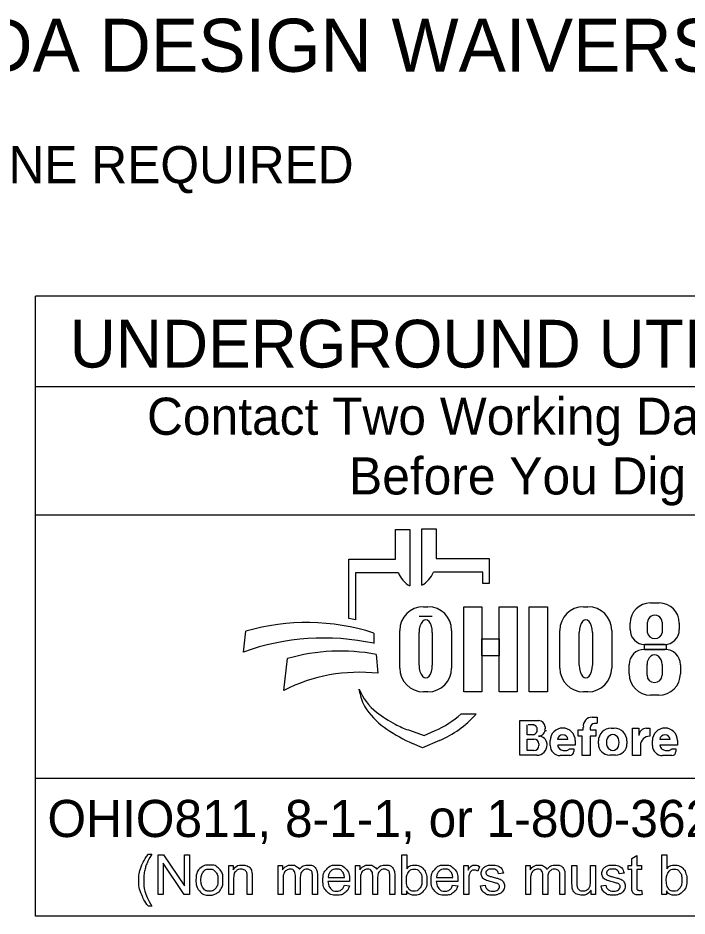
# Model space of a CAD drawing. Extents: x 0 to 34, y 0 to 22.
# Drawn here: x 2.311 to 4.831, y 2.143 to 5.529 of the extents above; entities that cross this region are included whole.
import ezdxf

# ---------------------------------------------------------------- set-up
doc = ezdxf.new("R2010")
doc.units = 0
doc.layers.add('SH_Data', color=7, linetype='Continuous')
doc.layers.add('SH_Text', color=7, linetype='Continuous')

msp = doc.modelspace()

# ---------------------------------------------------------------- linework, layer by layer
at = {"layer": 'SH_Data'}
for p, q in [((2.3775, 2.1428), (2.3775, 4.4803)), ((6.6275, 4.4803), (2.3775, 4.4803)), ((2.3775, 4.1387), (6.6275, 4.1387)), ((2.3775, 3.6553), (6.6275, 3.6553)), ((6.6275, 2.6607), (2.3775, 2.6607)), ((6.6275, 2.1428), (2.3775, 2.1428))]:
    msp.add_line(p, q, dxfattribs=at)
at = {"layer": 'SH_Text'}
for p, q in [((3.7335, 3.4883), (3.7335, 3.5998)), ((3.7335, 3.5998), (3.7872, 3.5998)), ((3.7872, 3.5998), (3.7872, 3.3877)), ((3.8329, 3.39), (3.8329, 3.6021)), ((3.8329, 3.6021), (3.8865, 3.6021)), ((3.8865, 3.6021), (3.8865, 3.4906)), ((3.5576, 3.2644), (3.5576, 3.4883)), ((3.5576, 3.4883), (3.7335, 3.4883)), ((3.8865, 3.4906), (4.0857, 3.4906)), ((4.0857, 3.4906), (4.0857, 3.3968)), ((3.5828, 3.4369), (3.5828, 3.26)), ((3.7439, 3.4369), (3.5828, 3.4369)), ((4.0625, 3.4392), (3.8761, 3.4392)), ((4.0625, 3.3968), (4.0625, 3.4392)), ((4.0857, 3.3968), (4.0625, 3.3968)), ((4.6931, 3.3231), (4.7258, 3.3231)), ((3.8385, 3.3091), (3.8551, 3.3091)), ((4.4416, 3.3091), (4.4581, 3.3091)), ((3.8718, 3.2721), (3.822, 3.2721)), ((4.683, 3.2111), (4.683, 3.2504)), ((4.7371, 3.2504), (4.7371, 3.2111)), ((3.7491, 3.0776), (3.7491, 3.2196)), ((3.9445, 3.2196), (3.9445, 3.0776)), ((4.3521, 3.0776), (4.3521, 3.2196)), ((4.5476, 3.2196), (4.5476, 3.0776)), ((4.6168, 3.2225), (4.6168, 3.2468)), ((4.8022, 3.2468), (4.8022, 3.2225)), ((3.1602, 3.1381), (3.1696, 3.2162)), ((3.6509, 3.2097), (3.6509, 3.1709)), ((3.822, 3.089), (3.822, 3.2114)), ((3.8718, 3.2114), (3.8718, 3.089)), ((4.425, 3.089), (4.425, 3.2114)), ((4.4748, 3.2114), (4.4748, 3.089)), ((4.7462, 3.1665), (4.6728, 3.1665)), ((3.6608, 3.1291), (3.6671, 3.0582)), ((4.671, 3.1482), (4.7483, 3.1482)), ((3.312, 2.9936), (3.3267, 3.1137)), ((4.6131, 3.0563), (4.6131, 3.0903)), ((4.6806, 3.0503), (4.6806, 3.0912)), ((4.7374, 3.0912), (4.7374, 3.0503)), ((4.8062, 3.0903), (4.8062, 3.0563)), ((3.5997, 2.9807), (3.5967, 2.9986)), ((3.8551, 2.9882), (3.8385, 2.9882)), ((4.4581, 2.9882), (4.4416, 2.9882)), ((4.7252, 2.9753), (4.6941, 2.9753)), ((3.98, 2.9048), (4.0375, 2.9048)), ((4.2013, 2.749), (4.2013, 2.8798)), ((4.2013, 2.8798), (4.2725, 2.8798)), ((4.4739, 2.8926), (4.4934, 2.8926)), ((4.4934, 2.8926), (4.4934, 2.8696)), ((3.7816, 2.8444), (3.841, 2.8239)), ((4.2293, 2.8263), (4.2293, 2.8632)), ((4.2545, 2.8632), (4.2332, 2.8632)), ((4.2963, 2.856), (4.2963, 2.8481)), ((4.4213, 2.8212), (4.4213, 2.8442)), ((4.4213, 2.8442), (4.4406, 2.8442)), ((4.4406, 2.8442), (4.4406, 2.8546)), ((4.4667, 2.8526), (4.4667, 2.8442)), ((4.4667, 2.8442), (4.4883, 2.8442)), ((4.4934, 2.8691), (4.4832, 2.8691)), ((4.4883, 2.8442), (4.4883, 2.8212)), ((4.5451, 2.8508), (4.5573, 2.8508)), ((4.6254, 2.7478), (4.6254, 2.8505)), ((4.6254, 2.8505), (4.6499, 2.8505)), ((4.6499, 2.8505), (4.6499, 2.8237)), ((4.6772, 2.8505), (4.691, 2.8505)), ((4.691, 2.8505), (4.691, 2.8209)), ((3.841, 2.8239), (3.8821, 2.8417)), ((4.2487, 2.8263), (4.2293, 2.8263)), ((4.4362, 2.8212), (4.4213, 2.8212)), ((4.4362, 2.7478), (4.4362, 2.8212)), ((4.4883, 2.8212), (4.4667, 2.8212)), ((4.4667, 2.8212), (4.4667, 2.7478)), ((3.835, 2.7769), (3.7976, 2.7934)), ((3.8983, 2.8044), (3.835, 2.7769)), ((4.2293, 2.7669), (4.2293, 2.8097)), ((4.2293, 2.8097), (4.2548, 2.8097)), ((4.2729, 2.7916), (4.2729, 2.7853)), ((4.3043, 2.7887), (4.3043, 2.7884)), ((4.3159, 2.7858), (4.3159, 2.8042)), ((4.3824, 2.8082), (4.3439, 2.8082)), ((4.4104, 2.7866), (4.344, 2.7866)), ((4.4104, 2.8042), (4.4104, 2.7866)), ((4.4973, 2.7922), (4.4973, 2.8029)), ((4.6051, 2.8029), (4.6051, 2.7922)), ((4.6559, 2.786), (4.6559, 2.7478)), ((4.7008, 2.7858), (4.7008, 2.8042)), ((4.7674, 2.8082), (4.7288, 2.8082)), ((4.7953, 2.7866), (4.7289, 2.7866)), ((4.7953, 2.8042), (4.7953, 2.7866)), ((4.265, 2.749), (4.2013, 2.749)), ((4.2546, 2.7669), (4.2293, 2.7669)), ((4.3892, 2.7478), (4.3538, 2.7478)), ((4.3649, 2.7673), (4.379, 2.7673)), ((4.3876, 2.7729), (4.4045, 2.7729)), ((4.4045, 2.7729), (4.4045, 2.7631)), ((4.4667, 2.7478), (4.4362, 2.7478)), ((4.5623, 2.7494), (4.5401, 2.7494)), ((4.6559, 2.7478), (4.6254, 2.7478)), ((4.7742, 2.7478), (4.7388, 2.7478)), ((4.7498, 2.7673), (4.7639, 2.7673)), ((4.7725, 2.7729), (4.7894, 2.7729)), ((4.7894, 2.7729), (4.7894, 2.7631))]:
    msp.add_line(p, q, dxfattribs=at)
for points in [[(3.991, 3.3081), (4.0589, 3.3081), (4.0589, 2.9881), (3.991, 2.9881)], [(4.1231, 3.3081), (4.1911, 3.3081), (4.1911, 2.9881), (4.1231, 2.9881)], [(4.2364, 3.3081), (4.3052, 3.3081), (4.3052, 2.9881), (4.2364, 2.9881)], [(4.0589, 3.1882), (4.1231, 3.1882), (4.1231, 3.1242), (4.0589, 3.1242)], [(4.6706, 3.1665), (4.7523, 3.1665), (4.7523, 3.1481), (4.6706, 3.1481)]]:
    msp.add_lwpolyline(points, close=True, dxfattribs=at)
for points in [[(2.8021, 2.3766), (2.8153, 2.3766)], [(2.8389, 2.2239), (2.8389, 2.3741), (2.8592, 2.3741), (2.9382, 2.2561), (2.9382, 2.3741), (2.9572, 2.3741), (2.9572, 2.2239), (2.9369, 2.2239), (2.8579, 2.3419), (2.8579, 2.2239), (2.8389, 2.2239)], [(3.7743, 2.2239), (3.7573, 2.2239), (3.7573, 2.3741), (3.7757, 2.3741), (3.7757, 2.3206)], [(4.6233, 2.2558), (4.6233, 2.3185), (4.6097, 2.3185), (4.6097, 2.3328), (4.6233, 2.3328), (4.6233, 2.3597), (4.6417, 2.3708), (4.6417, 2.3328), (4.6601, 2.3328), (4.6601, 2.3185), (4.6417, 2.3185), (4.6417, 2.2547)], [(4.7534, 2.2239), (4.7363, 2.2239), (4.7363, 2.3741), (4.7548, 2.3741), (4.7548, 2.3206)], [(3.1048, 2.2239), (3.1048, 2.3328), (3.1214, 2.3328), (3.1214, 2.3173)], [(3.2912, 2.2239), (3.2912, 2.3328), (3.3077, 2.3328), (3.3077, 2.3174)], [(3.5826, 2.2239), (3.5826, 2.3328), (3.5991, 2.3328), (3.5991, 2.3174)], [(3.9904, 2.2239), (3.9904, 2.3328), (4.007, 2.3328), (4.007, 2.3163)], [(4.0495, 2.3293), (4.043, 2.3122)], [(4.1394, 2.3046), (4.1213, 2.3022)], [(4.2236, 2.2239), (4.2236, 2.3328), (4.2401, 2.3328), (4.2401, 2.3174)], [(4.3979, 2.2654), (4.3979, 2.3328), (4.4164, 2.3328), (4.4164, 2.2724)], [(4.4676, 2.2745), (4.4676, 2.3328), (4.4861, 2.3328), (4.4861, 2.2239), (4.4696, 2.2239)], [(4.594, 2.3046), (4.5759, 2.3022)], [(3.1233, 2.2833), (3.1233, 2.2239), (3.1048, 2.2239)], [(3.1932, 2.2908), (3.1932, 2.2239), (3.1748, 2.2239), (3.1748, 2.2901)], [(3.3097, 2.2803), (3.3097, 2.2239), (3.2912, 2.2239)], [(3.3743, 2.2871), (3.3743, 2.2239), (3.3559, 2.2239), (3.3559, 2.2946)], [(3.4388, 2.2986), (3.4388, 2.2239), (3.4203, 2.2239), (3.4203, 2.2924)], [(3.56, 2.2736), (3.4788, 2.2736)], [(3.4799, 2.2887), (3.5406, 2.2887)], [(3.601, 2.2803), (3.601, 2.2239), (3.5826, 2.2239)], [(3.6657, 2.2871), (3.6657, 2.2239), (3.6473, 2.2239), (3.6473, 2.2946)], [(3.7301, 2.2986), (3.7301, 2.2239), (3.7117, 2.2239), (3.7117, 2.2924)], [(3.968, 2.2736), (3.8868, 2.2736)], [(3.8879, 2.2887), (3.9486, 2.2887)], [(4.0088, 2.2809), (4.0088, 2.2239), (3.9904, 2.2239)], [(4.242, 2.2803), (4.242, 2.2239), (4.2236, 2.2239)], [(4.3067, 2.2871), (4.3067, 2.2239), (4.2883, 2.2239), (4.2883, 2.2946)], [(4.3711, 2.2986), (4.3711, 2.2239), (4.3527, 2.2239), (4.3527, 2.2924)], [(3.5404, 2.2591), (3.5595, 2.2567)], [(3.7743, 2.2375), (3.7743, 2.2239)], [(3.9484, 2.2591), (3.9675, 2.2567)], [(4.053, 2.2564), (4.0712, 2.2593)], [(4.4696, 2.2239), (4.4696, 2.24)], [(4.5076, 2.2564), (4.5258, 2.2593)], [(4.6601, 2.2404), (4.6628, 2.2241)], [(4.7534, 2.2375), (4.7534, 2.2239)], [(2.8153, 2.1798), (2.8021, 2.1798)]]:
    msp.add_lwpolyline(points, dxfattribs=at)
for centre, radius, start, end in [((3.8353, 3.4736), 0.0985, 201.9296, 240.7469), ((3.7847, 3.476), 0.0985, 299.2531, 338.0704), ((4.6931, 3.2468), 0.0763, 90, 180), ((4.7258, 3.2468), 0.0763, 0, 90), ((3.8385, 3.2196), 0.0895, 90, 180), ((3.8551, 3.2196), 0.0895, 0, 90), ((4.4416, 3.2196), 0.0895, 90, 180), ((4.4581, 3.2196), 0.0895, 0, 90), ((3.4295, 2.4554), 0.8191, 79.2074, 81.0007), ((3.3997, 2.4302), 0.8191, 72.1402, 106.3144), ((4.6728, 3.2225), 0.056, 180, 270), ((4.7462, 3.2225), 0.056, 270, 0), ((3.4628, 2.2991), 0.8919, 77.8238, 109.8274), ((3.5267, 2.4094), 0.7322, 79.44, 105.8467), ((4.671, 3.0903), 0.0579, 90, 180), ((4.7483, 3.0903), 0.0579, 0, 90), ((3.5987, 2.4262), 0.6357, 83.8248, 116.8021), ((3.8385, 3.0776), 0.0895, 180, 270), ((3.8551, 3.0776), 0.0895, 270, 0), ((4.4416, 3.0776), 0.0895, 180, 270), ((4.4581, 3.0776), 0.0895, 270, 0), ((4.6941, 3.0563), 0.081, 180, 270), ((4.7252, 3.0563), 0.081, 270, 0), ((3.7841, 3.0707), 0.2008, 201.0457, 232.5314), ((3.741, 3.0048), 0.1433, 189.6817, 216.0884), ((3.8747, 3.1022), 0.3088, 216.0884, 235.7167), ((3.9766, 3.3219), 0.5173, 232.5314, 241.794), ((3.7387, 3.1722), 0.3602, 293.4582, 312.0712), ((3.7387, 3.1722), 0.401, 293.4582, 317.8286), ((4.2725, 2.856), 0.0238, 0, 90), ((4.4739, 2.859), 0.0335, 90, 187.5187), ((4.0412, 3.3465), 0.6044, 235.7167, 246.2325), ((3.8914, 3.1631), 0.3371, 241.794, 250.9821), ((4.2487, 2.845), 0.0187, 270, 2.0582), ((4.2505, 2.8463), 0.0169, 357.8325, 90), ((4.2721, 2.8453), 0.0243, 270, 6.6529), ((4.3631, 2.8042), 0.0473, 0, 180), ((4.4832, 2.8526), 0.0165, 90, 180), ((4.5451, 2.8029), 0.0478, 90, 180), ((4.5573, 2.8029), 0.0478, 0, 90), ((4.6768, 2.8237), 0.0269, 89.2449, 180), ((4.7481, 2.8042), 0.0473, 0, 180), ((4.2722, 2.7889), 0.0321, 4.0748, 90), ((4.2827, 2.8438), 0.0175, 347.4023, 0), ((4.3632, 2.8072), 0.0193, 2.9632, 177.0368), ((4.6908, 2.786), 0.0349, 89.6033, 180), ((4.7481, 2.8072), 0.0193, 2.9632, 177.0368), ((4.2546, 2.7853), 0.0184, 270, 0), ((4.2548, 2.7916), 0.0181, 0, 90), ((4.265, 2.7884), 0.0393, 270, 0), ((4.2714, 2.7887), 0.033, 0, 11.7502), ((4.3538, 2.7858), 0.038, 180, 270), ((4.3649, 2.7883), 0.021, 184.827, 270), ((4.5401, 2.7922), 0.0428, 180, 270), ((4.5623, 2.7922), 0.0428, 270, 0), ((4.7388, 2.7858), 0.038, 180, 270), ((4.7498, 2.7883), 0.021, 184.827, 270), ((4.379, 2.7767), 0.00938, 270, 335.9979), ((4.3892, 2.7631), 0.0152, 270, 0), ((4.7639, 2.7767), 0.00938, 270, 335.9979), ((4.7742, 2.7631), 0.0152, 270, 0)]:
    msp.add_arc(centre, radius, start, end, dxfattribs=at)
for centre, major_axis, ratio, start_param, end_param in [((3.8469, 3.2114), (0, 0.0484), 0.514403, 4.712389, 7.853982), ((4.4499, 3.2114), (0, 0.0484), 0.514403, 4.712389, 7.853982), ((4.71, 3.2504), (0.0271, 0), 0.969373, 0, 3.141593), ((4.71, 3.2111), (0.0271, 0), 0.818453, 3.141593, 6.283185), ((4.709, 3.0912), (0, 0.0358), 0.794529, 4.712389, 7.853982), ((3.8469, 3.089), (0, 0.0484), 0.514403, 1.570796, 4.712389), ((4.4499, 3.089), (0, 0.0484), 0.514403, 1.570796, 4.712389), ((4.709, 3.0503), (0.0284, 0), 0.959837, 3.141593, 6.283185), ((4.5517, 2.7976), (0, 0.029), 0.832186, 4.712389, 7.853982), ((4.5517, 2.7976), (0, 0.0302), 0.797287, 1.570796, 4.712389)]:
    msp.add_ellipse(centre, major_axis=major_axis, ratio=ratio, start_param=start_param, end_param=end_param, dxfattribs=at)
for points in [[(2.8021, 2.1798), (2.7869, 2.199), (2.7763, 2.2248), (2.7657, 2.2506), (2.7657, 2.2783), (2.7657, 2.3026), (2.7736, 2.325), (2.7829, 2.3509), (2.8021, 2.3766)], [(2.8153, 2.3766), (2.8029, 2.3553), (2.7989, 2.3462), (2.7927, 2.332), (2.7891, 2.3167), (2.7847, 2.2975), (2.7847, 2.2782), (2.7847, 2.2289), (2.8153, 2.1798)], [(2.9814, 2.2783), (2.9814, 2.3085), (2.9981, 2.3231), (3.0122, 2.3352), (3.0323, 2.3352), (3.0547, 2.3352), (3.069, 2.3205), (3.0832, 2.3058), (3.0832, 2.2799), (3.0832, 2.2589), (3.0769, 2.2469), (3.0706, 2.2348), (3.0586, 2.2282), (3.0466, 2.2215), (3.0323, 2.2215), (3.0095, 2.2215), (2.9954, 2.2362), (2.9814, 2.2508), (2.9814, 2.2783)], [(3.0003, 2.2783), (3.0003, 2.2574), (3.0094, 2.247), (3.0185, 2.2366), (3.0323, 2.2366), (3.046, 2.2366), (3.0551, 2.2471), (3.0642, 2.2575), (3.0642, 2.279), (3.0642, 2.2991), (3.0551, 2.3095), (3.0459, 2.3199), (3.0323, 2.3199), (3.0185, 2.3199), (3.0094, 2.3096), (3.0003, 2.2992), (3.0003, 2.2783)], [(3.1214, 2.3173), (3.1334, 2.3352), (3.156, 2.3352), (3.1659, 2.3352), (3.1741, 2.3316), (3.1823, 2.3281), (3.1864, 2.3224), (3.1905, 2.3166), (3.1922, 2.3087), (3.1932, 2.3036), (3.1932, 2.2908)], [(3.1748, 2.2901), (3.1748, 2.3013), (3.1726, 2.3069), (3.1705, 2.3125), (3.165, 2.3158), (3.1595, 2.3191), (3.1521, 2.3191), (3.1404, 2.3191), (3.1318, 2.3117), (3.1233, 2.3042), (3.1233, 2.2833)], [(3.3077, 2.3174), (3.3128, 2.3254), (3.3214, 2.3303), (3.3299, 2.3352), (3.3407, 2.3352), (3.3528, 2.3352), (3.3606, 2.3301), (3.3683, 2.3251), (3.3715, 2.3161), (3.3844, 2.3352), (3.4051, 2.3352), (3.4213, 2.3352), (3.43, 2.3262), (3.4388, 2.3172), (3.4388, 2.2986)], [(3.3559, 2.2946), (3.3559, 2.3069), (3.3514, 2.313), (3.3469, 2.3191), (3.3366, 2.3191), (3.3288, 2.3191), (3.3222, 2.315), (3.3156, 2.311), (3.3126, 2.3031), (3.3097, 2.2952), (3.3097, 2.2803)], [(3.4203, 2.2924), (3.4203, 2.3035), (3.4185, 2.3083), (3.4168, 2.3132), (3.412, 2.3162), (3.4073, 2.3191), (3.401, 2.3191), (3.3895, 2.3191), (3.3819, 2.3115), (3.3743, 2.3039), (3.3743, 2.2871)], [(3.5595, 2.2567), (3.555, 2.24), (3.5428, 2.2307), (3.5306, 2.2215), (3.5117, 2.2215), (3.4878, 2.2215), (3.4738, 2.2362), (3.4598, 2.2509), (3.4598, 2.2774), (3.4598, 2.3049), (3.474, 2.32), (3.4881, 2.3352), (3.5106, 2.3352), (3.5324, 2.3352), (3.5463, 2.3203), (3.5601, 2.3055), (3.5601, 2.2785), (3.5601, 2.2769), (3.56, 2.2736)], [(3.5406, 2.2887), (3.5394, 2.3025), (3.5337, 2.3094), (3.5249, 2.3201), (3.5108, 2.3201), (3.4981, 2.3201), (3.4894, 2.3115), (3.4808, 2.303), (3.4799, 2.2887)], [(3.5991, 2.3174), (3.6042, 2.3254), (3.6127, 2.3303), (3.6212, 2.3352), (3.6321, 2.3352), (3.6442, 2.3352), (3.6519, 2.3301), (3.6597, 2.3251), (3.6628, 2.3161), (3.6758, 2.3352), (3.6965, 2.3352), (3.7127, 2.3352), (3.7214, 2.3262), (3.7301, 2.3172), (3.7301, 2.2986)], [(3.6473, 2.2946), (3.6473, 2.3069), (3.6428, 2.313), (3.6383, 2.3191), (3.628, 2.3191), (3.6202, 2.3191), (3.6136, 2.315), (3.607, 2.311), (3.604, 2.3031), (3.601, 2.2952), (3.601, 2.2803)], [(3.7117, 2.2924), (3.7117, 2.3035), (3.7099, 2.3083), (3.7081, 2.3132), (3.7034, 2.3162), (3.6987, 2.3191), (3.6923, 2.3191), (3.6809, 2.3191), (3.6733, 2.3115), (3.6657, 2.3039), (3.6657, 2.2871)], [(3.7741, 2.2792), (3.7741, 2.2596), (3.7794, 2.2509), (3.7881, 2.2366), (3.8029, 2.2366), (3.815, 2.2366), (3.8238, 2.2471), (3.8326, 2.2576), (3.8326, 2.2784), (3.8326, 2.2998), (3.8241, 2.3099), (3.8157, 2.3201), (3.8038, 2.3201), (3.7917, 2.3201), (3.7829, 2.3096), (3.7741, 2.299), (3.7741, 2.2792)], [(3.7757, 2.3206), (3.7874, 2.3352), (3.8055, 2.3352), (3.8155, 2.3352), (3.8245, 2.3311), (3.8335, 2.3271), (3.8392, 2.3198), (3.845, 2.3124), (3.8483, 2.3021), (3.8516, 2.2918), (3.8516, 2.28), (3.8516, 2.252), (3.8378, 2.2368), (3.8239, 2.2215), (3.8046, 2.2215), (3.7853, 2.2215), (3.7743, 2.2375)], [(3.9675, 2.2567), (3.963, 2.24), (3.9508, 2.2307), (3.9386, 2.2215), (3.9196, 2.2215), (3.8958, 2.2215), (3.8818, 2.2362), (3.8678, 2.2509), (3.8678, 2.2774), (3.8678, 2.3049), (3.882, 2.32), (3.8961, 2.3352), (3.9186, 2.3352), (3.9404, 2.3352), (3.9543, 2.3203), (3.9681, 2.3055), (3.9681, 2.2785), (3.9681, 2.2769), (3.968, 2.2736)], [(3.9486, 2.2887), (3.9474, 2.3025), (3.9417, 2.3094), (3.9328, 2.3201), (3.9188, 2.3201), (3.9061, 2.3201), (3.8974, 2.3115), (3.8888, 2.303), (3.8879, 2.2887)], [(4.007, 2.3163), (4.0133, 2.3278), (4.0187, 2.3315), (4.0241, 2.3352), (4.0305, 2.3352), (4.0398, 2.3352), (4.0495, 2.3293)], [(4.043, 2.3122), (4.0363, 2.3162), (4.0295, 2.3162), (4.0235, 2.3162), (4.0187, 2.3125), (4.0139, 2.3089), (4.0119, 2.3024), (4.0088, 2.2926), (4.0088, 2.2809)], [(4.1213, 2.3022), (4.1201, 2.3106), (4.1142, 2.3153), (4.1083, 2.3201), (4.0975, 2.3201), (4.0848, 2.3201), (4.0794, 2.3159), (4.0739, 2.3116), (4.0739, 2.306), (4.0739, 2.3024), (4.0762, 2.2995), (4.0785, 2.2966), (4.0833, 2.2946), (4.086, 2.2936), (4.0996, 2.2899), (4.1192, 2.2847), (4.1269, 2.2813), (4.1347, 2.278), (4.1391, 2.2717), (4.1435, 2.2653), (4.1435, 2.2559), (4.1435, 2.2467), (4.1381, 2.2386), (4.1327, 2.2304), (4.1226, 2.226), (4.1124, 2.2215), (4.0996, 2.2215), (4.0784, 2.2215), (4.0672, 2.2303), (4.0561, 2.2391), (4.053, 2.2564)], [(4.0712, 2.2593), (4.0727, 2.2483), (4.0798, 2.2425), (4.0868, 2.2366), (4.0995, 2.2366), (4.1122, 2.2366), (4.1184, 2.2418), (4.1245, 2.247), (4.1245, 2.254), (4.1245, 2.2602), (4.1191, 2.2638), (4.1153, 2.2663), (4.1002, 2.2701), (4.0799, 2.2752), (4.072, 2.2789), (4.0642, 2.2827), (4.0601, 2.2893), (4.0561, 2.2959), (4.0561, 2.3038), (4.0561, 2.3111), (4.0594, 2.3173), (4.0628, 2.3235), (4.0685, 2.3276), (4.0728, 2.3308), (4.0803, 2.333), (4.0877, 2.3352), (4.0962, 2.3352), (4.109, 2.3352), (4.1187, 2.3315), (4.1284, 2.3278), (4.133, 2.3215), (4.1377, 2.3152), (4.1394, 2.3046)], [(4.2401, 2.3174), (4.2452, 2.3254), (4.2537, 2.3303), (4.2622, 2.3352), (4.2731, 2.3352), (4.2852, 2.3352), (4.2929, 2.3301), (4.3007, 2.3251), (4.3038, 2.3161), (4.3168, 2.3352), (4.3375, 2.3352), (4.3537, 2.3352), (4.3624, 2.3262), (4.3711, 2.3172), (4.3711, 2.2986)], [(4.2883, 2.2946), (4.2883, 2.3069), (4.2838, 2.313), (4.2793, 2.3191), (4.269, 2.3191), (4.2612, 2.3191), (4.2546, 2.315), (4.248, 2.311), (4.245, 2.3031), (4.242, 2.2952), (4.242, 2.2803)], [(4.3527, 2.2924), (4.3527, 2.3035), (4.3509, 2.3083), (4.3491, 2.3132), (4.3444, 2.3162), (4.3397, 2.3191), (4.3333, 2.3191), (4.3219, 2.3191), (4.3143, 2.3115), (4.3067, 2.3039), (4.3067, 2.2871)], [(4.5759, 2.3022), (4.5747, 2.3106), (4.5688, 2.3153), (4.5629, 2.3201), (4.5521, 2.3201), (4.5394, 2.3201), (4.5339, 2.3159), (4.5285, 2.3116), (4.5285, 2.306), (4.5285, 2.3024), (4.5308, 2.2995), (4.533, 2.2966), (4.5378, 2.2946), (4.5406, 2.2936), (4.5542, 2.2899), (4.5737, 2.2847), (4.5815, 2.2813), (4.5893, 2.278), (4.5937, 2.2717), (4.5981, 2.2653), (4.5981, 2.2559), (4.5981, 2.2467), (4.5927, 2.2386), (4.5873, 2.2304), (4.5772, 2.226), (4.567, 2.2215), (4.5542, 2.2215), (4.5329, 2.2215), (4.5218, 2.2303), (4.5107, 2.2391), (4.5076, 2.2564)], [(4.5258, 2.2593), (4.5273, 2.2483), (4.5343, 2.2425), (4.5414, 2.2366), (4.554, 2.2366), (4.5668, 2.2366), (4.5729, 2.2418), (4.5791, 2.247), (4.5791, 2.254), (4.5791, 2.2602), (4.5736, 2.2638), (4.5698, 2.2663), (4.5548, 2.2701), (4.5345, 2.2752), (4.5266, 2.2789), (4.5188, 2.2827), (4.5147, 2.2893), (4.5107, 2.2959), (4.5107, 2.3038), (4.5107, 2.3111), (4.514, 2.3173), (4.5173, 2.3235), (4.5231, 2.3276), (4.5274, 2.3308), (4.5348, 2.333), (4.5423, 2.3352), (4.5508, 2.3352), (4.5636, 2.3352), (4.5733, 2.3315), (4.583, 2.3278), (4.5876, 2.3215), (4.5922, 2.3152), (4.594, 2.3046)], [(4.7532, 2.2792), (4.7532, 2.2596), (4.7585, 2.2509), (4.7672, 2.2366), (4.782, 2.2366), (4.7941, 2.2366), (4.8029, 2.2471), (4.8116, 2.2576), (4.8116, 2.2784), (4.8116, 2.2998), (4.8032, 2.3099), (4.7948, 2.3201), (4.7828, 2.3201), (4.7708, 2.3201), (4.762, 2.3096), (4.7532, 2.299), (4.7532, 2.2792)], [(4.7548, 2.3206), (4.7664, 2.3352), (4.7846, 2.3352), (4.7946, 2.3352), (4.8036, 2.3311), (4.8125, 2.3271), (4.8183, 2.3198), (4.8241, 2.3124), (4.8274, 2.3021), (4.8306, 2.2918), (4.8306, 2.28), (4.8306, 2.252), (4.8168, 2.2368), (4.803, 2.2215), (4.7836, 2.2215), (4.7644, 2.2215), (4.7534, 2.2375)], [(3.4788, 2.2736), (3.4799, 2.2557), (3.489, 2.2462), (3.4981, 2.2366), (3.5117, 2.2366), (3.5219, 2.2366), (3.5291, 2.242), (3.5362, 2.2473), (3.5404, 2.2591)], [(3.8868, 2.2736), (3.8879, 2.2557), (3.897, 2.2462), (3.9061, 2.2366), (3.9197, 2.2366), (3.9299, 2.2366), (3.937, 2.242), (3.9442, 2.2473), (3.9484, 2.2591)], [(4.4164, 2.2724), (4.4164, 2.258), (4.4175, 2.253), (4.4192, 2.2457), (4.4249, 2.2416), (4.4305, 2.2374), (4.4388, 2.2374), (4.4471, 2.2374), (4.4543, 2.2417), (4.4616, 2.2459), (4.4646, 2.2533), (4.4676, 2.2606), (4.4676, 2.2745)], [(4.4696, 2.24), (4.4569, 2.2215), (4.4351, 2.2215), (4.4255, 2.2215), (4.4171, 2.2252), (4.4088, 2.2289), (4.4047, 2.2345), (4.4007, 2.2401), (4.3991, 2.2482), (4.3979, 2.2536), (4.3979, 2.2654)], [(4.6628, 2.2241), (4.655, 2.2224), (4.6488, 2.2224), (4.6388, 2.2224), (4.6333, 2.2256), (4.6278, 2.2288), (4.6255, 2.234), (4.6233, 2.2392), (4.6233, 2.2558)], [(4.6417, 2.2547), (4.6417, 2.2468), (4.6427, 2.2445), (4.6436, 2.2423), (4.6458, 2.2409), (4.648, 2.2396), (4.6521, 2.2396), (4.6551, 2.2396), (4.6601, 2.2404)]]:
    msp.add_open_spline(points, degree=3, dxfattribs=at)

# ---------------------------------------------------------------- texts
for s, height, p in [('ADA DESIGN WAIVERS', 0.2, (1.9944, 5.3256)), ('NONE REQUIRED', 0.14, (1.9944, 4.9056)), ('UNDERGROUND UTILITIES', 0.18, (2.5057, 4.2106)), ('Contact Two Working Days', 0.14, (2.7972, 3.9571)), ('Before You Dig', 0.14, (3.5583, 3.7321)), ('OHIO811, 8-1-1, or 1-800-362-2764', 0.14, (2.422, 2.4406))]:
    msp.add_text(s, height=height, dxfattribs=at).set_placement(p)

doc.saveas('drawing.dxf')
